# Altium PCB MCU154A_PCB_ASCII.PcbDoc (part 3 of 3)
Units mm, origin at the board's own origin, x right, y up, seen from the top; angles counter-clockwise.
Board outline 105 x 85 mm, 2 copper layers (Top Layer, Bottom Layer), stack 1.6 mm thick; 186 components, 100 nets, 433 pads, 196 vias.
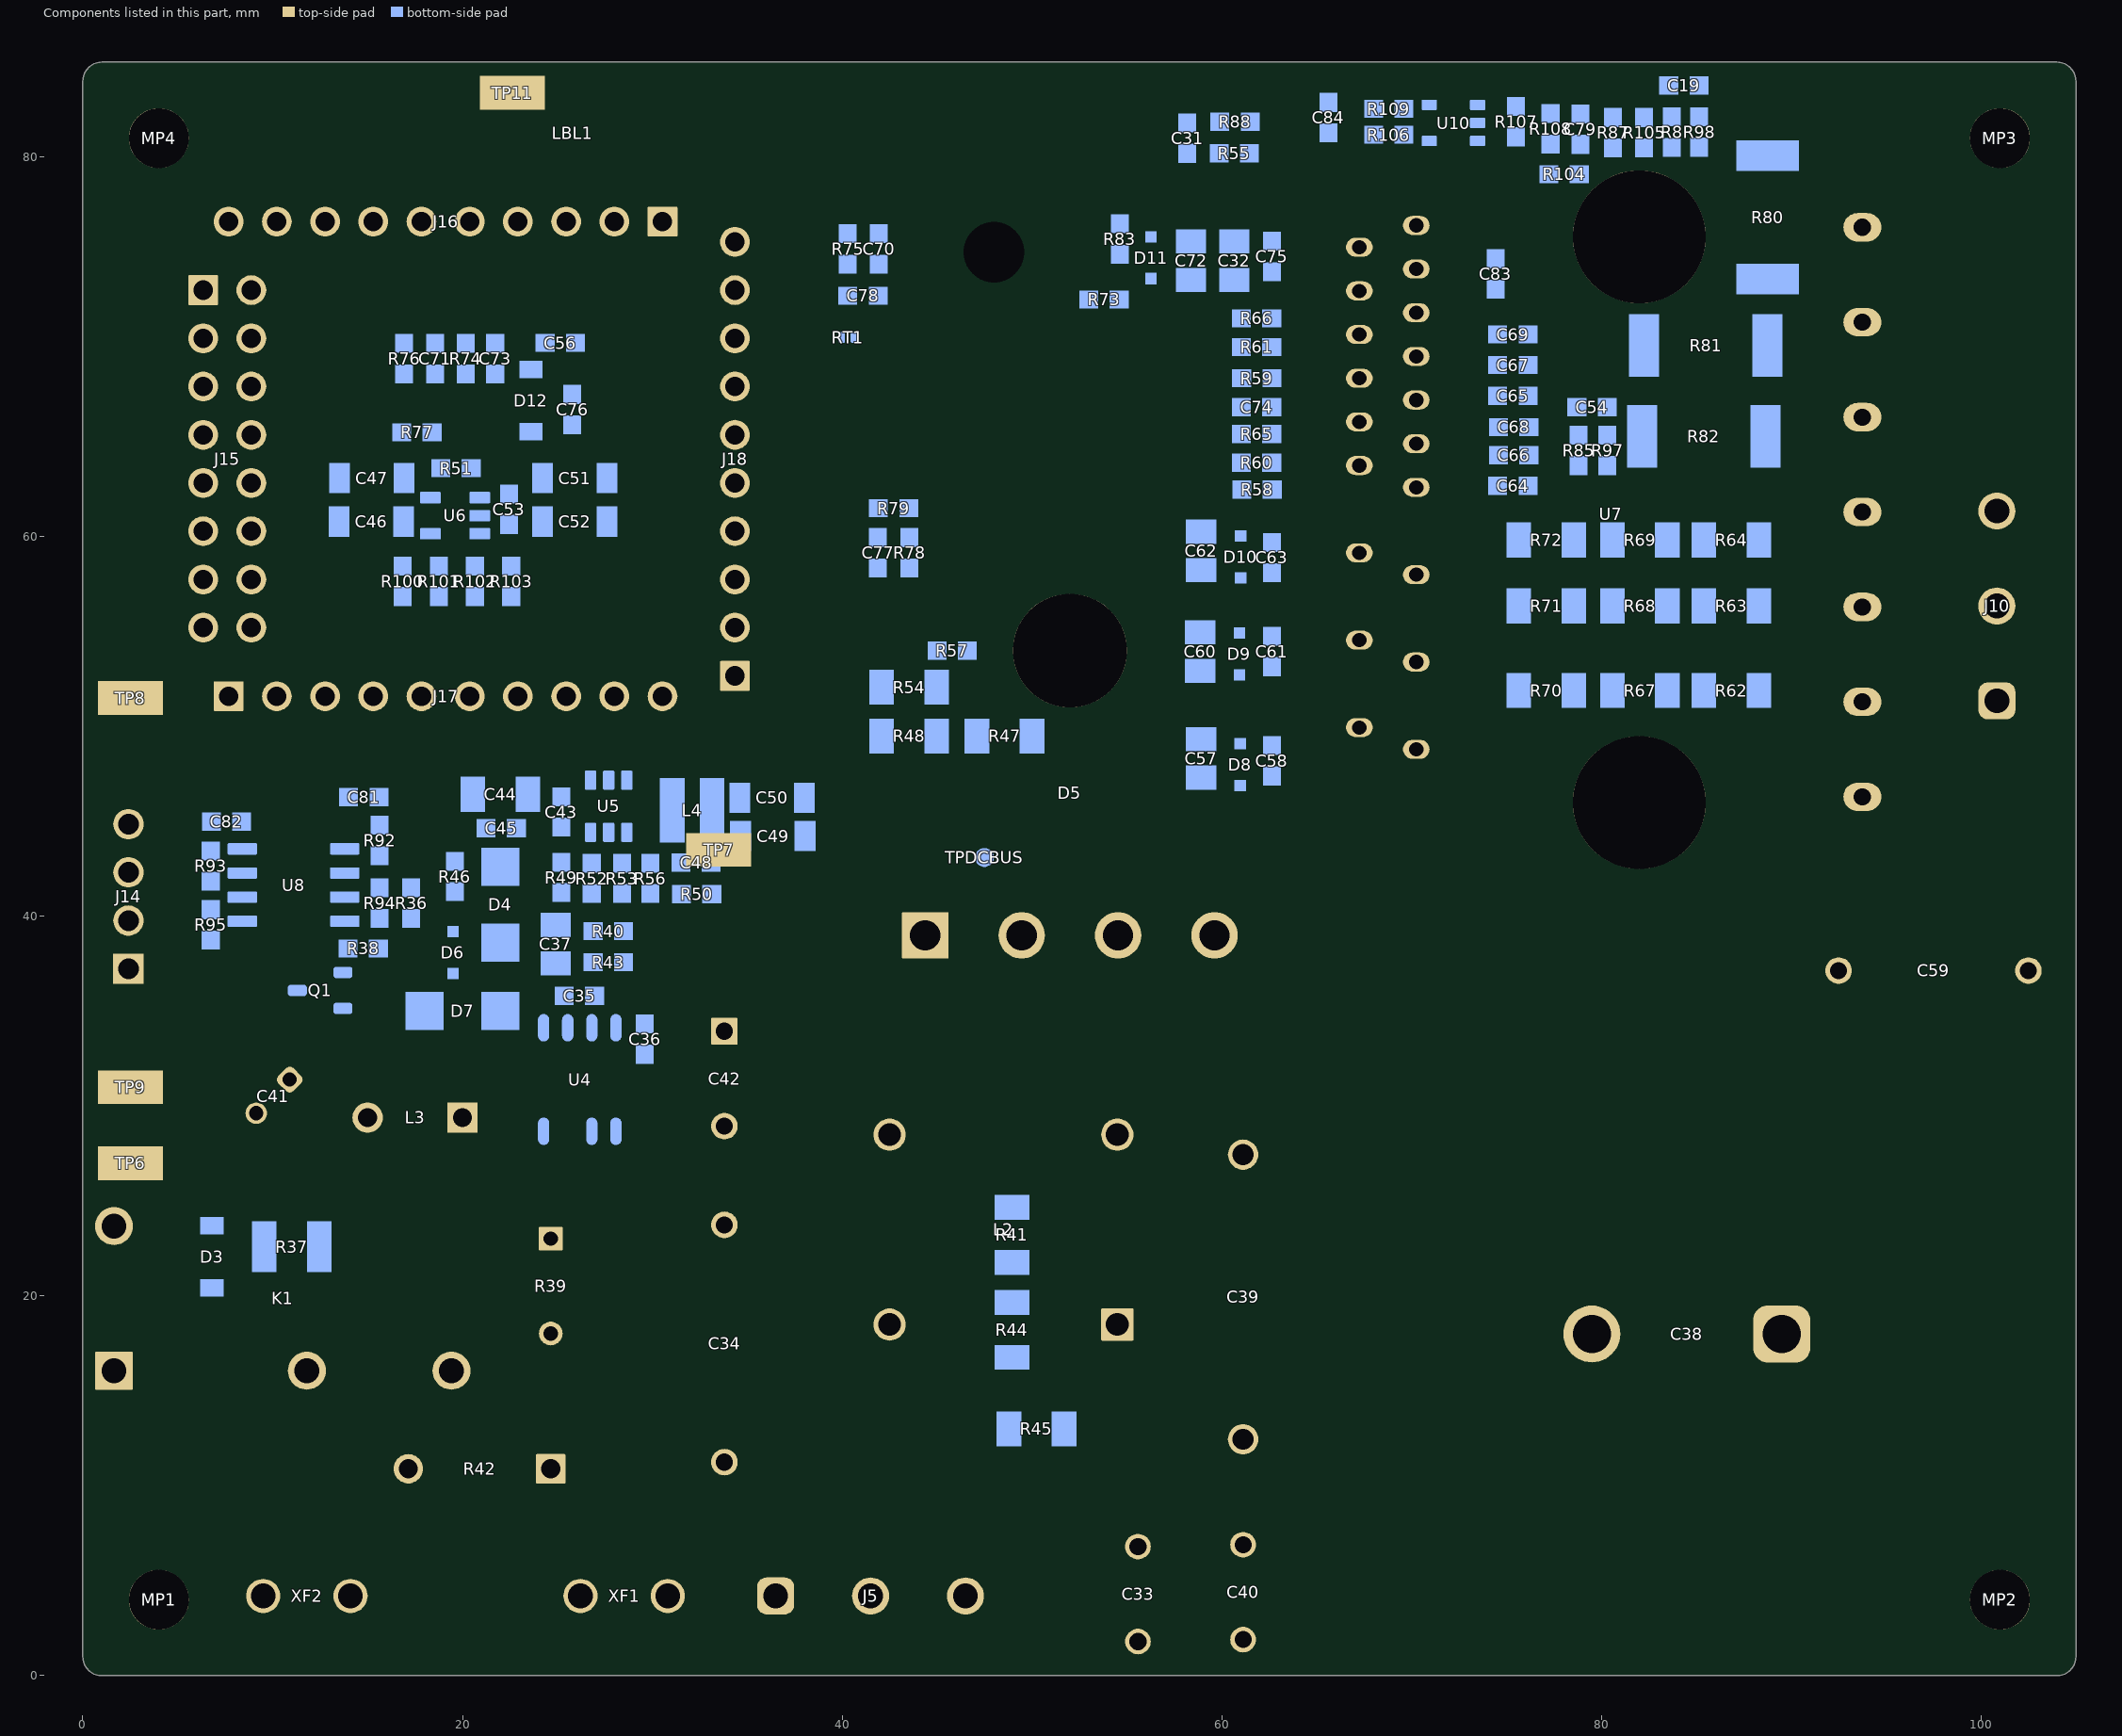
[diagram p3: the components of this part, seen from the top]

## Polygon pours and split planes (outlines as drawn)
NetC35_2 on Bottom Layer "TOP_LAYER_NONET_P-001" (solid, pour order 93): 20.909,33.309 18.616,31.016 18.616,28.772 18.907,28.481 20.862,28.481 21.238,28.857 21.238,30.171 24.11,33.044 25.531,33.044 25.545,33.029 25.931,33.415 25.931,36.75 25.923,36.851 26.13,37.058 27.259,37.058 27.4,37.199 27.4,38.1 27.3,38.2 24.332,38.2 22.332,36.2 21.17,36.2 20.909,35.94
MOTOR_V on Bottom Layer "TOP_LAYER_NONET_P-001" (solid, pour order 89): 92.18,54.223 91.853,54.55 91.853,57.925 92.328,58.4 102.868,58.4 103.389,57.6 103.389,54.9 102.868,54.223
MOTOR_W on Bottom Layer "TOP_LAYER_NONET_P-001" (solid, pour order 88): 93.13,59.616 92.405,60.34 92.405,62.047 93.144,62.786 96.301,62.786 97.675,64.161 98.283,64.5 104.102,64.5 104.5,64.161 104.5,62.21 101.913,59.623
MOTOR_U on Bottom Layer "TOP_LAYER_NONET_P-001" (solid, pour order 87): 92.405,52.8 91.9,52.295 91.9,49.826 92.556,49.17 95.677,49.17 99.193,47.7 103.055,47.7 104.5,49.17 104.5,50.3 102,52.8
EGND on Bottom Layer "TOP_LAYER_NONET_P-001" (solid, pour order 86): 45.4,4.2 45.4,1.3 46.2,0.6 62.388,0.6 63.188,1.4 63.188,2.512 62.7,3 49.47,3 48.789,3.681 48.789,6.9 48.359,6.9 45.8,6.9 45.4,6.389
NEU on Bottom Layer "TOP_LAYER_NONET_P-001" (solid, pour order 20): 22.3,10.3 23.1,9.5 37.8,9.5 40,7.3 40,3.3 40.7,2.512 42.5,2.512 43,3.2 43,7.7 44.8,9.5 44.8,19.48 44.28,20 38.898,20 34.058,15.16 31.498,12.6 23.12,12.6 22.3,11.78
LINE on Bottom Layer "TOP_LAYER_NONET_P-001" (solid, pour order 51): 22,1.3 22.6,0.7 36.3,0.7 37.7,2.1 37.7,5.7 36.5,6.9 22.5,6.9 22,6.4
5V on Bottom Layer "T-G" (solid, remove dead copper, pour order 83): 23.116,61.7 23.92,60.895 24.756,60.895 24.756,64.068 24.591,64.233 20.218,64.233 19.968,63.983 19.968,62.422 19.247,61.7 19.247,59.705 19.403,59.549 21.643,59.549 21.674,59.579 21.674,60.323 21.533,60.463 20.068,60.463 19.968,60.563 19.968,61.363 20.305,61.7
5V on Bottom Layer "B-5V" (solid, remove dead copper, pour order 84): 32.5,47.309 34.844,47.309 35.399,46.754 35.399,40.395 35.108,40.103 33.037,40.103 32.5,40.64
Ubus on Bottom Layer "Bottom Layer-Ubus" (solid, pour order 16): 91.438,0.6 103.77,12.932 103.77,38.93 95,47.7 92.69,47.7 92.319,47.328 92.319,41.378 95.5,38.196 95.5,35.935 94.531,34.966 92.306,34.966 85.972,41.3 80.866,41.3 76.571,45.595 55.965,45.595 54.379,47.181 41.932,47.181 40.764,46.013 40.764,37.615 41.302,36.75 45.768,36.75 46.268,37.25 46.268,41.214 47.105,42.052 62.554,42.052 70.25,34.355 70.25,2.343 71.993,0.6
NetR8_1 on Bottom Layer "Bottom Layer-NetR8_1" (solid, pour order 80): 94.716,73.06 103.571,73.06 104.23,73.718 104.23,76.505 103.777,76.957 98.863,76.957 96.7,79.12 96.7,83.613 96.223,84.09 91.761,84.09 91.216,83.545 91.216,78.53 91.204,78.518 91.204,77.912 88.856,75.564 87.358,75.564 85.803,75.564 85.397,75.158 85.397,73.157 85.837,72.717 90.254,72.717 90.59,73.053 94.709,73.053
GND on Bottom Layer "Bottom Layer-GND" (solid, pour order 74): 85.874,78.556 86.88,77.55 89.757,77.55 90.59,78.384 90.59,84.26 90.276,84.574 86.616,84.574 85.874,83.833
NetR55_1 on Bottom Layer "Bottom Layer-NetR55_1" (solid, pour order 78): 88.002,68.059 89.581,68.059 89.581,68.068 90.478,68.068 91.035,68.624 95.103,68.624 96.473,69.994 104.004,69.994 104.004,72.307 103.594,72.717 93.7,72.717 93.7,72.723 93.694,72.717 91.684,72.717 90.724,71.757 86.357,71.757 85.96,71.36 85.96,68.523 86.423,68.059 88.002,68.059
NetC34_1 on Bottom Layer "TOP_LAYER_NONET_P-001" (solid, pour order 53): 17,18.6 19.5,21.1 26.711,21.1 31.512,25.901 36.299,25.901 41.283,30.886 44.196,30.886 45.19,29.892 45.19,23.223 43.9,21.933 38.033,21.933 30.75,14.65 17.25,14.65 17,14.9
NetK1_2 on Bottom Layer "TOP_LAYER_NONET_P-001" (solid, pour order 50): 8,0.988 8,8 6.093,9.907 6.093,17.402 7.291,18.6 13.3,18.6 15.055,16.845 15.055,15.525 18.5,12.08 18.5,1.6 17.5,0.6 8.3,0.6
NetR82_2 on Bottom Layer "TOP_LAYER_NONET_P-001" (solid, pour order 33): 90.265,66.924 91.622,68.281 94.813,68.281 95.2,67.893 95.2,64.815 94.709,64.325 91.761,64.325 91.091,63.654 87.916,63.654 87.916,66.826 88.015,66.924
NetR82_2 on Bottom Layer "TOP_LAYER_NONET_P-001" (solid, pour order 32): 89.495,63.373 86.338,63.373 85.874,63.836 85.874,66.673 86.271,67.07 89.388,67.07 89.495,66.963
GND on Bottom Layer "TOP_LAYER_NONET_P-001" (solid, pour order 29): 81.376,71.925 84.633,71.925 85.097,71.462 85.097,68.624 84.7,68.228 81.583,68.228 81.376,68.434
GND on Bottom Layer "TOP_LAYER_NONET_P-001" (solid, pour order 28): 81.376,67.297 84.533,67.297 84.997,66.834 84.997,63.997 84.6,63.6 81.483,63.6 81.376,63.707
Ubus on Bottom Layer "TOP_LAYER_NONET_P-001" (solid, pour order 17): 23.583,29.25 23.583,27.225 24.058,26.75 34.221,26.75 35.724,28.253 35.724,29.255 34.811,30.168 31.514,30.168 30.815,29.469 28.013,29.469 27.68,29.136 27.68,27.861 27.587,27.768 24.83,27.768 24.65,27.948 24.65,29.291 24.472,29.469 23.809,29.469
NetC39_2 on Bottom Layer "TOP_LAYER_NONET_P-001" (solid, pour order 6): 53.511,21.488 63.188,21.488 64.644,22.944 64.644,29.931 63.247,31.328 56.61,31.328 53.1,34.838 53.1,39.9 53.762,40.562 55.624,40.562 55.9,40.285 55.9,36.65 57.55,35 65.2,35 68.4,31.8 68.4,19.1 65.2,15.9 65.1,16 53.19,16 52.387,16.803 52.387,20.469
NetC33_1 on Bottom Layer "TOP_LAYER_NONET_P-001" (solid, pour order 5): 48.712,24 47.99,24.722 47.99,39.645 48.907,40.562 50.239,40.562 50.9,39.901 50.9,33.981 55.826,29.054 61.283,29.054 62.198,28.14 62.198,24.694 61.504,24
GND_ISO on Top Layer "T-G" (solid, remove dead copper, pour order 94): 8.9,46.25 0.9,46.25 0.7,46.05 0.7,36.174 1.024,35.85 5.45,35.85 9.2,39.6 9.2,45.95
GND on Top Layer "Top Layer-GND 1" (solid, remove dead copper, pour order 64): 19.5,36.502 20.068,37.071 20.068,40.068 20.424,40.424 29.702,40.424 29.998,40.078 31.544,38.531 31.544,33.388 32.196,32.737 35.107,32.737 35.661,33.29 35.661,37.268 38.729,40.336 38.729,47.732 39.797,48.8 47.74,48.8 48.7,49.76 48.7,55.495 55.242,62.037 73.539,62.037 74.153,61.423 74.153,50.69 74.594,50.249 76.279,50.249 77.365,51.334 77.365,60.129 79.027,61.791 80.146,61.791 80.579,62.224 80.579,72.27 78.541,74.307 78.541,77.41 80.552,79.421 85.293,79.421 85.627,79.756 85.627,84.384 85.211,84.8 9.7,84.8 8.484,83.584 8.484,78.408 7.676,77.6 2.034,77.6 0.706,76.272 0.706,50 10.116,50 13,47.085 13,38.627 6.373,32 0.6,32 0.6,26.227 1.069,25.758 15.988,25.758 16.5,26.27 16.5,31.166 18.722,33.388 19.5,34.166
MOTOR_V on Top Layer "TOP_LAYER_NONET_P-001" (solid, pour order 26): 92.18,54.223 91.853,54.55 91.853,57.925 92.328,58.4 102.868,58.4 103.389,57.6 103.389,54.9 102.868,54.223
MOTOR_U on Top Layer "TOP_LAYER_NONET_P-001" (solid, pour order 24): 92.405,52.8 91.9,52.295 91.9,49.826 92.556,49.17 95.677,49.17 99.193,47.7 103.055,47.7 104.5,49.17 104.5,50.3 102,52.8
MOTOR_W on Top Layer "TOP_LAYER_NONET_P-001" (solid, pour order 25): 93.13,59.616 92.405,60.34 92.405,62.047 93.144,62.786 96.301,62.786 97.675,64.161 98.283,64.5 104.102,64.5 104.5,64.161 104.5,62.21 101.913,59.623
EGND on Top Layer "TOP_LAYER_NONET_P-001" (solid, pour order 54): 45.4,4.2 45.4,1.3 46.2,0.6 62.388,0.6 63.188,1.4 63.188,2.512 62.7,3 49.47,3 48.789,3.681 48.789,6.9 48.359,6.9 45.8,6.9 45.4,6.389
NEU on Top Layer "TOP_LAYER_NONET_P-001" (solid, pour order 85): 22.3,10.3 23.1,9.5 37.8,9.5 40,7.3 40,3.3 40.7,2.512 42.5,2.512 43,3.2 43,7.7 44.8,9.5 44.8,19.48 44.28,20 38.898,20 34.058,15.16 31.498,12.6 23.12,12.6 22.3,11.78
LINE on Top Layer "TOP_LAYER_NONET_P-001" (solid, pour order 19): 22,1.3 22.6,0.7 36.3,0.7 37.7,2.1 37.7,5.7 36.5,6.9 22.5,6.9 22,6.4
GND on Top Layer "Top Layer-GND" (solid, pour order 82): 57.876,38.224 58.731,37.369 64.852,37.369 70.25,31.971 70.25,2.45 72.1,0.6 91.438,0.6 103.9,13.062 103.9,29.745 94.164,39.481 92.325,41.32 92.312,41.32 89.283,44.349 89.283,76.766 89.474,76.957 90.59,78.074 90.59,84.26 90.276,84.574 86.616,84.574 85.902,83.861 85.902,79.22 85.346,78.664 85.346,74.379 83.275,72.307 81.607,72.307 81.1,71.8 81.1,50.249 81.42,49.929 83.703,49.929 85.589,48.043 85.589,43.147 84.437,41.994 80.146,41.994 77.111,45.029 59.256,45.029 57.876,43.648
NetC33_1 on Top Layer "TOP_LAYER_NONET_P-001" (solid, pour order 55): 49.913,24 47.99,25.923 47.99,39.645 48.907,40.562 50.239,40.562 50.9,39.901 50.9,33.981 55.826,29.054 61.283,29.054 62.198,28.14 62.198,24.694 61.504,24
NetR55_1 on Top Layer "Top Layer-NetR55_1" (solid, pour order 77): 89.513,68.068 90.478,68.068 91.035,68.624 95.103,68.624 96.473,69.994 104.004,69.994 104.004,72.307 103.594,72.717 93.7,72.717 93.7,72.723 93.694,72.717 91.684,72.717 90.724,71.757 89.513,71.757
NetR8_1 on Top Layer "Top Layer-NetR8_1" (solid, pour order 70): 94.716,73.06 103.571,73.06 104.23,73.718 104.23,76.505 103.777,76.957 98.863,76.957 96.7,79.12 96.7,83.613 96.223,84.09 91.761,84.09 91.216,83.545 91.216,78.53 91.204,78.518 91.204,77.912 90.141,76.849 89.498,76.206 89.498,72.717 90.254,72.717 90.59,73.053 94.709,73.053
NetR82_2 on Top Layer "TOP_LAYER_NONET_P-001" (solid, pour order 39): 89.547,66.938 90.281,66.94 91.622,68.281 94.813,68.281 95.2,67.893 95.2,64.815 94.709,64.325 91.761,64.325 91.072,63.636 89.547,63.636
Ubus on Top Layer "TOP_LAYER_NONET_P-001" (solid, pour order 60): 94.999,47.7 103.9,38.799 103.9,35.896 103.658,35.654 102.275,35.654 101.002,36.927 93.791,44.138 92.319,45.61 92.319,47.328 92.69,47.7
NetC39_2 on Top Layer "TOP_LAYER_NONET_P-001" (solid, pour order 56): 53.511,21.488 63.188,21.488 64.644,22.944 64.644,29.931 63.247,31.328 56.61,31.328 53.1,34.838 53.1,39.9 53.762,40.562 55.624,40.562 55.9,40.285 55.9,36.65 57.55,35 65.2,35 68.4,31.8 68.4,19.1 65.2,15.9 65.1,16 53.19,16 52.387,16.803 52.387,20.469
NetC34_1 on Top Layer "TOP_LAYER_NONET_P-001" (solid, pour order 21): 17.611,19.211 19.1,20.7 26.311,20.7 31.512,25.901 36.299,25.901 41.283,30.886 44.196,30.886 45.19,29.892 45.19,23.223 43.9,21.933 38.033,21.933 30.75,14.65 18.121,14.65 17.611,15.16
NetK1_2 on Top Layer "TOP_LAYER_NONET_P-001" (solid, pour order 18): 8,0.988 8,8 6.093,9.907 6.093,17.402 7.291,18.6 13.283,18.6 15.055,16.829 15.055,15.345 18.5,11.9 18.5,1.6 17.5,0.6 8.3,0.6

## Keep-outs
Top Layer:
  circle w0.254: c48,75 r2.5
Bottom Layer:
  circle w0.254: c48,75 r3.5
Keep-Out Layer:
  circle w0.254: c4,81 r4
  circle w0.254: c101,81 r4
  circle w0.254: c101,4 r4
  circle w0.254: c4,4 r4
  text ".Layer_Name" at 14.656,-21.806 h1.52

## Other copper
Top Layer:
  text ".Layer_Name" at 14.656,-21.806 h1.52
Bottom Layer:
  text ".Layer_Name" at 14.656,-21.806 h1.52

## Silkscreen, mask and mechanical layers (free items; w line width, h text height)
Top Overlay:
  circle w0.254: c84.5,18 r15.892
  lines w0.2: 0.86,56.44 4.86,56.44 ; 0.86,59.94 4.86,59.94 ; 0.86,61.94 4.86,61.94 ; 0.86,64.94 4.86,64.94 ; 0.86,67.94 4.86,67.94 ; 0.86,70.94 4.86,70.94 ; 0.86,73.94 4.86,73.94 ; 2.86,52.94 2.86,76.94 ; 6.464,39.394 9.6,39.394 ; 6.464,41.015 9.6,41.015 ; 6.464,42.614 9.6,42.614 ; 6.469,44.063 9.6,44.063 9.6,37.906 9.568,37.874 6.481,37.874 ; 8.95,78.194 8.95,82.194 ; 9.55,45.206 9.55,49.706 ; 11.49,82.194 11.49,78.194 ; 12.09,45.206 12.09,49.706 ; 14.03,78.194 14.03,82.194 ; 14.63,45.206 14.63,49.706 ; 16.57,78.194 16.57,82.194 ; 17.17,45.206 17.17,49.706 ; 19.11,78.194 19.11,82.194 ; 19.71,45.206 19.71,49.706 ; 21.65,82.194 21.65,78.194 ; 22.25,45.206 22.25,49.706 ; 24.19,82.194 24.19,78.194 ; 24.79,45.206 24.79,49.706 ; 26.73,82.194 26.73,78.194 ; 27.33,45.206 27.33,49.706 ; 29.27,78.194 29.27,82.194 ; 29.87,45.206 29.87,49.706 ; 36.354,53.94 39.354,53.94 ; 36.354,64.1 39.354,64.1 ; 36.354,66.64 39.354,66.64 ; 36.354,69.18 39.354,69.18 ; 36.354,74.26 39.354,74.26 ; 39.354,56.48 36.354,56.48 ; 39.354,59.02 36.354,59.02 ; 39.354,61.56 36.354,61.56 ; 39.354,71.72 36.354,71.72 ; 11.49,78.194 21.65,78.194 ; 11.49,78.194 6.41,78.194 6.41,82.194 31.81,82.194 31.81,78.194 26.73,78.194 ; 21.65,78.194 24.19,78.194 ; 24.19,78.194 26.73,78.194 ; 36.354,56.48 36.354,51.4 39.354,51.4 39.354,76.8 36.354,76.8 36.354,71.72 ; 36.354,56.48 36.354,59.02 ; 36.354,59.02 36.354,61.56 ; 36.354,61.56 36.354,71.72 ; 0.86,52.94 0.86,76.94 4.86,76.94 4.86,52.94 0.86,52.94 ; 7.01,45.206 7.01,49.706 32.41,49.706 32.41,45.206 7.01,45.206
  text "GND" at 25.3,82.9 h0.9
  text "IUN" at 8.17,79.025 h0.9 r90
  text "IUP" at 10.721,79.025 h0.9 r90
  text "IVN" at 13.272,79.025 h0.9 r90
  text "IVP" at 15.823,79.025 h0.9 r90
  text "IWN" at 25.928,79.025 h0.9 r90
  text "IWP" at 28.479,79.025 h0.9 r90
  text "GND" at 18.375,78.95 h0.9 r90
  text "VWAD" at 20.826,78.683 h0.8 r90
  text "VUAD" at 23.377,78.5 h0.9 r90
  text "VVAD" at 31.03,78.5 h0.9 r90
  text "VDC" at 36.608,75.04 h0.9
  text "3V3" at 2.3,74.26 h0.9 r90
  text "GND" at 4.3,74.26 h0.9 r90
  text "IPM" at 36.683,72.5 h0.9
  text "TMS" at 2.3,71.14 h0.9 r90
  text "TCK" at 4.3,71.14 h0.9 r90
  text "MOT" at 36.608,69.96 h0.9
  text "W" at 101.15,69.758 h1.5 r90
  text "TDI" at 2.3,68.4 h0.9 r90
  text "TDO" at 4.3,68.14 h0.9 r90
  text "WH" at 37.058,67.42 h0.9
  text "V" at 101.206,67.32 h1.5 r90
  text "GND" at 2.3,65.2 h0.9 r90
  text "WL" at 37.058,64.88 h0.9
  text "RX" at 2.3,62.7 h0.9 r90
  text "TX" at 4.3,62.7 h0.9 r90
  text "GND" at 36.608,62.204 h0.9
  text "UH" at 37.058,59.8 h0.9
  text "UL" at 37.058,57.26 h0.9
  text "CLK" at 2.3,57.1 h0.9 r90
  text "PICO" at 4.3,56.64 h0.9 r90
  text "VH" at 37.058,54.72 h0.9
  text "POCI" at 2.3,53.2 h0.9 r90
  text "PTE" at 4.3,53.2 h0.9 r90
  text "VL" at 37.058,52.18 h0.9
  text "3.3V" at 3.215,49.1 h0.8
  text "IO" at 11.31,46.885 h0.9 r90
  text "CLK" at 18.93,46.36 h0.9 r90
  text "PTE" at 21.47,46.36 h0.9 r90
  text "3V3" at 26.55,46.36 h0.9 r90
  text "GND" at 29.09,46.36 h0.9 r90
  text "POCI" at 24.01,46.06 h0.9 r90
  text "PICO" at 16.39,45.985 h0.9 r90
  text "RELAY" at 8.77,45.46 h0.9 r90
  text "FAULT" at 31.63,45.46 h0.9 r90
  text "U" at 101.498,44.5 h1.5 r90
  text "Isolated UART" at 10.049,43.892 h0.75 r270
  text "5V" at 31.967,41.1 h0.8
  text "5V / RX / TX / GND" at 6.737,38.026 h0.9
  text "'.PRJ_TITLE' / '.PRJ_Number'.PCB_Rev" at 64.376,34.594 h2.75
  text "GND" at 3.687,32.601 h0.8
  text "15V" at 3.437,28.611 h0.8
  text "+" at 94.265,17.295 h1.25
  text "拼板" at 397.247,13.207 h4
  text "L" at 36.05,8.15 h1.5
  text "N" at 40.95,8.05 h1.5
  text "E" at 46.05,7.95 h1.5
  text ".Layer_Name" at 14.656,-21.806 h1.52
Bottom Overlay:
  lines w0.2: 29.892,40.476 30.267,40.101 31.6,40.101 32,39.701 ; 86.24,81.914 86.655,81.914 ; 86.254,82.489 86.254,81.928 86.226,81.9 87.033,82.707 88.347,82.707
  lines w0.254: 62.78,4.194 79.98,4.194 ; 62.78,7.194 79.98,7.194 ; 65.422,10.094 65.481,1.358 ; 94.05,20.722 102.75,20.781 ; 97.05,7.081 97.05,35.261 ; 99.95,7.081 99.95,35.201 ; 62.78,1.358 79.98,1.358 79.98,10.094 62.78,10.094 62.78,1.358 ; 94.05,7.081 94.05,35.261 102.85,35.261 102.85,7.081 94.05,7.081
  text "W" at 99.358,61.904 h1.5 r90
  text "V" at 99.369,56.847 h1.5 r90
  text "U" at 99.381,51.757 h1.5 r90
  text "'.Output_P' / '.Output_I' / '.Output_F_Motor'" at 102.75,35.081 h2 r90
  text "Rated Output Spec to Motor" at 93.55,35.061 h0.9 r90
  text "P / I / Motor F" at 102.75,20.725 h2 r90
  text "Rated AC Input Spec" at 79.78,10.594 h0.9
  text "L" at 37.15,5.638 h1.5
  text "N" at 42.05,5.538 h1.5
  text "E" at 47.15,5.438 h1.5
  text "V / I / F" at 65.2,1.494 h2
  text "'.Input_V' / '.Input_I' / '.Input_F'" at 79.8,1.494 h2
  text ".Layer_Name" at 14.656,-21.806 h1.52
Top Paste:
  text ".Layer_Name" at 14.656,-21.806 h1.52
Bottom Paste:
  text ".Layer_Name" at 14.656,-21.806 h1.52
Top Solder:
  text ".Layer_Name" at 14.656,-21.806 h1.52
  text ".Layer_Name" at 14.656,-21.806 h1.52
Bottom Solder:
  text ".Layer_Name" at 14.656,-21.806 h1.52
Drill Guide:
  text ".Layer_Name" at 14.656,-21.806 h1.52
M1 Board Outline:
  lines w0.2: 38.348,6.7 cw(c38.848,6.7) 39.348,6.7 39.348,1.5 cw(c38.848,1.5) 38.348,1.5 38.348,6.7 ; 44.651,1.5 44.651,6.7 ccw(c44.151,6.7) 43.651,6.7 43.652,1.5 ccw(c44.151,1.5) 44.651,1.5 ; 395.6,32.8 cw(c395.6,33.8) 394.6,33.8 394.6,136.8 cw(c395.6,136.8) 395.6,137.8 ; 395.6,32.8 cw(c395.6,32.3) 395.6,31.8 394.6,31.8 394.6,29.8 ccw(c396.6,29.8) 396.6,27.8 562.6,27.8 ccw(c562.6,29.8) 564.6,29.8 564.6,31.8 563.6,31.8 cw(c563.6,32.3) 563.6,32.8 ; 395.6,32.8 478.6,32.8 ; 395.6,137.8 ccw(c395.6,138.3) 395.6,138.8 394.6,138.8 394.6,140.8 cw(c396.6,140.8) 396.6,142.8 562.6,142.8 cw(c562.6,140.8) 564.6,140.8 564.6,138.8 563.6,138.8 ccw(c563.6,138.3) 563.6,137.8 ; 395.6,137.8 478.6,137.8 ; 478.6,32.8 ccw(c478.6,33.8) 479.6,33.8 ; 478.6,32.8 ccw(c478.6,32.3) 478.6,31.8 480.6,31.8 ccw(c480.6,32.3) 480.6,32.8 ; 478.6,137.8 cw(c478.6,136.8) 479.6,136.8 ; 478.6,137.8 cw(c478.6,138.3) 478.6,138.8 480.6,138.8 cw(c480.6,138.3) 480.6,137.8 ; 479.6,33.8 ccw(c480.6,33.8) 480.6,32.8 ; 479.6,33.8 479.6,136.8 ; 479.6,33.8 479.6,136.8 ; 479.6,136.8 cw(c480.6,136.8) 480.6,137.8 ; 480.6,32.8 563.6,32.8 ; 480.6,137.8 563.6,137.8 ; 563.6,32.8 ccw(c563.6,33.8) 564.6,33.8 564.6,136.8 ccw(c563.6,136.8) 563.6,137.8 ; 0,1 ccw(c1,1) 1,0 104,0 ccw(c104,1) 105,1 105,84 ccw(c104,84) 104,85 1,85 ccw(c1,84) 0,84 0,1 ; 4.36,50.6 ccw(c5.36,50.6) 5.36,49.6 35.36,49.6 ccw(c35.36,50.6) 36.36,50.6 36.36,77.6 ccw(c35.36,77.6) 35.36,78.6 5.36,78.6 ccw(c5.36,77.6) 4.36,77.6 4.36,50.6 ; 92.017,47.918 cw(c92.017,48.418) 92.017,48.918 95.6,48.918 99.673,44.845 cw(c99.319,44.491) 98.966,44.138 95.185,47.918 92.017,47.918 ; 92.017,52.995 cw(c92.017,53.495) 92.017,53.995 103,53.995 cw(c103,53.495) 103,52.995 92.017,52.995 ; 92.209,58.554 cw(c92.209,59.054) 92.209,59.554 103,59.554 cw(c103,59.054) 103,58.554 92.209,58.554 ; 92.695,63.017 cw(c92.695,63.517) 92.695,64.017 95.402,64.017 95.514,64.017 95.988,64.492 95.988,66.431 cw(c96.488,66.431) 96.988,66.431 96.988,64.115 95.89,63.017 92.695,63.017
  text ".Layer_Name" at 14.656,-21.806 h1.52
M2 Board Dimensions:
  rectangle: 0,-6.985 3.175,-3.81
  rectangle: 3.175,-10.16 12.7,-6.985
  lines w0.178: 0,-6.985 25.4,-6.985 ; 3.175,-10.16 3.175,-3.81 ; 6.35,-10.16 6.35,-3.81 ; 12.7,-10.16 12.7,-3.81 ; 19.05,-10.16 19.05,-3.81 ; 0,-10.16 25.4,-10.16 25.4,-3.81 0,-3.81 0,-10.16
  lines w0.254: 40.5,41 95.5,41 95.5,81 40.5,81 40.5,41
  text "41.5,34.8" at 87.948,77.32 h0.8
  text "7.5,34" at 43.5,69.067 h0.8
  text "11.5,13" at 46.9,48.618 h0.8
  text "41.5,5" at 79.691,38.704 h0.8
  text ".Layer_Name" at 14.656,-21.806 h1.52
M3 3D STEP Top:
  text ".Layer_Name" at 14.656,-21.806 h1.52
M4 3D STEP Bottom:
  text ".Layer_Name" at 14.656,-21.806 h1.52
M5 Assembly Top:
  lines w0.254: -7.417,-23.626 160.223,-23.626 ; -7.417,-18.462 160.274,-18.462 ; -7.417,-13.297 -7.417,-28.791 94.31,-28.791 160.274,-28.791 160.274,-13.297 -7.404,-13.297 -7.404,-28.791 32.614,-28.791 ; 55.194,-28.791 55.194,-13.297 ; 87.376,-18.462 87.376,-13.297 ; 108.712,-18.462 108.712,-13.297 ; 124.511,-28.956 124.511,-23.804
  text "COMPONENTS MARKED 'DNP' SHOULD NOT BE POPULATED." at 29.299,-8.09 h0.8
  text "ASSEMBLY VARIANT:" at 29.286,-11.024 h0.8
  text ".VariantName" at 55.601,-11.024 h0.8
  text "PCB VIEWED FROM TOP SIDE" at -5.804,-16.654 h1.52
  text "BOARD #:" at 57.099,-16.654 h1.52
  text ".PRJ_Number" at 70.955,-16.654 h1.52
  text "REV:" at 92.405,-16.654 h1.52
  text ".PCB_Rev" at 99.809,-16.654 h1.52
  text "SVN REV:" at 113.69,-16.654 h1.52
  text ".VersionControl_RevNumber" at 126.543,-16.654 h1.52
  text "TID #:" at 57.099,-21.819 h1.52
  text ".TID" at 70.955,-21.819 h1.52
  text "PLOT NAME =" at -5.804,-27.034 h1.52
  text ".plot_File_Name" at 14.656,-27.034 h1.52
  text "GENERATED    :" at 57.15,-27.034 h1.52
  text ".Print_Date" at 79.235,-27.034 h1.52
  text ".Print_Time" at 97.752,-27.034 h1.52
  text "TEXAS INSTRUMENTS" at 129.87,-27.034 h1.52
M6 Assembly Bottom:
  lines w0.254: -7.429,-18.474 160.261,-18.474 ; -7.379,-23.639 160.261,-23.639 ; 28.334,-28.969 28.334,-23.817 ; 44.133,-18.474 44.133,-13.31 ; 65.468,-18.474 65.468,-13.31 ; 97.65,-28.804 97.65,-13.31 ; 120.231,-28.804 160.249,-28.804 160.249,-13.31 -7.429,-13.31 -7.429,-28.804 58.534,-28.804 160.261,-28.804 160.261,-13.31
  text "COMPONENTS MARKED 'DNP' SHOULD NOT BE POPULATED." at 154.991,-8.077 h0.8
  text ".VariantName" at 128.473,-11.024 h0.8
  text "ASSEMBLY VARIANT:" at 154.864,-11.024 h0.8
  text ".VersionControl_RevNumber" at 26.302,-16.667 h1.52
  text "SVN REV:" at 39.154,-16.667 h1.52
  text ".PCB_Rev" at 53.035,-16.667 h1.52
  text "REV:" at 60.439,-16.667 h1.52
  text ".PRJ_Number" at 81.89,-16.667 h1.52
  text "BOARD #:" at 95.745,-16.667 h1.52
  text "PCB VIEWED FROM BOTTOM SIDE" at 158.648,-16.667 h1.52
  text ".TID" at 81.89,-21.831 h1.52
  text "TID #:" at 95.745,-21.831 h1.52
  text "TEXAS INSTRUMENTS" at 22.974,-27.047 h1.52
  text ".Print_Time" at 55.093,-27.047 h1.52
  text ".Print_Date" at 73.609,-27.047 h1.52
  text "GENERATED    :" at 95.694,-27.047 h1.52
  text ".plot_File_Name" at 138.189,-27.047 h1.52
  text "PLOT NAME =" at 158.648,-27.047 h1.52
M9 Title Sheet:
  lines w0.254: -12.484,26.454 -7.404,26.454 ; -12.484,86.779 -7.404,86.779 ; -12.484,147.104 -7.404,147.104 ; 51.016,-33.871 51.016,-28.791 ; 51.016,202.349 51.016,207.429 ; 114.516,-33.871 114.516,-28.791 ; 114.516,202.349 114.516,207.429 ; 160.553,-28.791 160.553,-13.297 287.109,-13.297 ; 178.016,-33.871 178.016,-28.791 ; 178.016,202.349 178.016,207.429 ; 241.516,-33.871 241.516,-28.791 ; 241.516,202.349 241.516,207.429 ; 287.109,-28.791 287.109,-13.297 ; 287.109,-20.917 363.309,-20.917 ; 287.109,-5.677 363.309,-5.677 ; 287.134,9.411 363.334,9.411 ; 305.016,-33.871 305.016,-28.791 ; 305.016,202.349 305.016,207.429 ; 325.336,-28.537 325.336,-13.297 ; 363.309,-13.297 287.109,-13.297 ; 363.309,1.943 287.109,1.943 ; 363.436,1.689 363.436,-28.791 ; 363.436,22.123 287.134,22.123 287.109,22.123 287.109,9.411 287.109,1.943 ; 363.436,26.454 368.516,26.454 ; 363.436,86.779 368.516,86.779 ; 363.436,147.104 368.516,147.104 ; 287.109,-13.297 287.109,1.943 ; 363.436,-28.791 363.436,202.349 -7.404,202.349 -7.404,-28.791 363.436,-28.791 ; -12.484,-33.871 -12.484,207.429 368.516,207.429 368.516,-33.871 -12.484,-33.871
  text "1" at 18.792,204.127 h1.78
  text "2" at 82.182,204.127 h1.78
  text "3" at 145.411,204.127 h1.78
  text "4" at 209.08,204.127 h1.78
  text "5" at 272.555,204.127 h1.78
  text "6" at 336.182,204.127 h1.78
  text "A" at -10.579,175.095 h1.78
  text "A" at 365.341,175.095 h1.78
  text "B" at -10.579,114.643 h1.78
  text "B" at 365.341,114.643 h1.78
  text "C" at -10.579,54.318 h1.78
  text "C" at 365.341,54.318 h1.78
  text "PROJECT TITLE:" at 288.125,7.048 h1.14
  text ".PRJ_Title" at 289.395,3.662 h1.78
  text "DESIGNED FOR:" at 288.125,-0.597 h1.14
  text ".PRJ_Customer" at 289.395,-4.153 h1.78
  text "D" at -10.579,-5.88 h1.78
  text "D" at 365.341,-5.88 h1.78
  text "FILE NAME:" at 288.125,-8.217 h1.14
  text ".PCB_File_Name_No_Path" at 289.395,-11.265 h1.78
  text "Texas Instruments (TI) and/or its licensors do not warrant the accuracy or completeness of this specification" at 161.9,-15.376 h1.14
  text "ENGINEER:" at 288.125,-15.583 h1.14
  text "LAYOUT BY:" at 326.352,-15.583 h1.14
  text "or any information contained therein. TI and/or its licensors do not warrant that this design will meet" at 160.757,-18.237 h1.14
  text ".PRJ_Engineer" at 289.395,-19.52 h1.78
  text ".PCB_Layout" at 327.635,-19.52 h1.78
  text "the specifications, will be suitable for your application or fit for any particular purpose, or will operate in" at 160.757,-21.099 h1.14
  text ".Layer_Name" at 14.656,-21.806 h1.52
  text "ALTIUM DESIGNER VERSION:" at 326.352,-23.457 h1.14
  text "an implementation. TI and/or its licensors do not warrant that the design is production worthy. You should" at 160.757,-23.961 h1.14
  text "completely validate and test your design implementation to confirm the system functionality for your application." at 161.9,-26.822 h1.14
  text ".print_Scale" at 289.395,-26.843 h1.78
  text ".Application_BuildNumber" at 327.635,-26.843 h1.78
  text "1" at 18.792,-32.093 h1.78
  text "2" at 82.182,-32.093 h1.78
  text "3" at 145.411,-32.093 h1.78
  text "4" at 209.08,-32.093 h1.78
  text "5" at 272.555,-32.093 h1.78
  text "6" at 336.182,-32.093 h1.78
M10 Fab Notes:
  drawing of 189 lines, arcs and shapes, not listed
  text "DESIGN INFORMATION" at 314.503,161.447 h1.52
  text "MIN. TRACK WIDTH:" at 298.131,158.091 h1.52
  text "8" at 325.976,158.091 h1.52
  text "MIL" at 329.907,158.091 h1.52
  text "MIN. CLEARANCE:" at 298.131,154.938 h1.52
  text "MIL" at 329.907,154.938 h1.52
  text "8" at 326.2,154.8 h1.52
  text "MIN. VIA PAD SIZE:" at 298.131,151.785 h1.52
  text "19" at 325.214,151.785 h1.52
  text "MIL" at 329.907,151.785 h1.52
  text "0.05mm (2MIL)" at 315.784,148.486 h1.52
  text "MINIMUM ANNULAR RING" at 289.769,148.277 h1.52
  text "EXTERNAL" at 333.768,148.277 h1.52
  text "PER" at 294.849,145.48 h1.52
  text "IPC-D-275 CLASS 2 LEVEL C" at 300.437,145.48 h1.52
  text "MIL, HOLES" at 338.238,142.928 h1.52
  text "+/-" at 328.27,142.709 h1.52
  text "+/-" at 349.961,142.709 h1.52
  text "REGISTRATION TOLERANCES:" at 289.769,142.682 h1.52
  text "METAL" at 320.243,142.682 h1.52
  text "5" at 334.879,142.683 h1.52
  text "3" at 356.037,142.683 h1.52
  text "MIL" at 358.99,142.682 h1.52
  text "HOLE SIZE TOLERANCE (UNLESS OTHERWISE SPECIFIED):" at 289.769,140.185 h1.52
  text "+/-" at 349.961,140.112 h1.52
  text "3" at 356.037,140.085 h1.52
  text "MIL" at 358.99,140.085 h1.52
  text "MATERIAL:" at 287.87,136.589 h1.52
  text "FR-4 High Tg" at 312.926,133.324 h1.52
  text "X" at 309.257,133.122 h1.52
  text "FR-4" at 298.563,133.007 h1.52
  text "OTHER" at 336.358,133.007 h1.52
  text "62 MIL (1.6mm) +/-10%" at 306.694,129.374 h1.52
  text "X" at 303.643,129.312 h1.52
  text "THICKNESS:" at 289.769,129.165 h1.52
  text "OTHER" at 339.33,129.165 h1.52
  text "TOLERANCE:" at 289.769,125.652 h1.52
  text "X" at 311.314,125.652 h1.52
  text "ANSI IPC-6012 TYPE 3 CLASS 2" at 315.836,125.652 h1.52
  text "OTHER +/-" at 315.835,121.989 h1.52
  text "BOW & TWIST:" at 289.769,118.302 h1.52
  text "X" at 311.314,118.302 h1.52
  text "ANSI IPC-6012 TYPE 3 CLASS 2" at 315.836,118.302 h1.52
  text "OTHER +/-" at 315.835,114.576 h1.52
  text "DRILLING:" at 287.87,111.258 h1.52
  text "NC_DRILL FILES" at 332.599,108.586 h1.52
  text "REFERENCE:" at 289.769,108.486 h1.52
  text "X" at 306.463,108.484 h1.52
  text "AS SHOWN" at 310.984,108.486 h1.52
  text "X" at 329.348,108.486 h1.52
  text "OTHER" at 340.168,104.873 h1.52
  text "PTH COPPER THICKNESS:" at 289.761,104.783 h1.52
  text "X" at 318.697,104.783 h1.52
  text "20-30 um" at 321.948,104.783 h1.52
  text "BOARD FINISH:" at 287.87,101.034 h1.52
  text "SILKSCREEN:" at 291.812,98.237 h1.52
  text "X" at 316.14,98.237 h1.52
  text "TOP" at 319.112,98.237 h1.52
  text "X" at 329.094,98.237 h1.52
  text "BOTTOM" at 332.091,98.237 h1.52
  text "SILKSCREEN COLOR:" at 291.812,94.295 h1.52
  text "X" at 316.115,94.295 h1.52
  text "WHITE" at 319.112,94.295 h1.52
  text "OTHER" at 332.091,94.295 h1.52
  text "X" at 319.442,90.652 h1.52
  text "GREEN" at 322.439,90.652 h1.52
  text "OTHER" at 338.136,90.652 h1.52
  text "SOLDER RESIST COLOR:" at 291.812,90.477 h1.52
  text "X" at 319.442,86.734 h1.52
  text "MATTE" at 322.439,86.734 h1.52
  text "SEMI-GLOSS" at 338.125,86.717 h1.52
  text "IMMERSION GOLD (ENIG)" at 314.819,82.345 h1.52
  text "ENEPIG" at 348.793,82.162 h1.52
  text "SURFACE FINISH:" at 287.87,82.136 h1.52
  text "HASL" at 342.237,78.762 h1.52
  text "IMM. TIN/SILVER OR EQUIV" at 296.24,78.649 h1.52
  text "X" at 328.078,78.549 h1.52
  text "OTHER" at 332.599,78.549 h1.52
  text "ARRAY/PANEL:" at 287.87,74.602 h1.52
  text "CUT AND TRIM PER M1 BOARD OUTLINE" at 314.819,74.393 h1.52
  text "N.C. ROUTE" at 314.819,70.94 h1.52
  text "X" at 332.295,70.94 h1.52
  text "V. SCORE" at 336.816,70.94 h1.52
  text "CERTIFICATION:" at 287.87,67.66 h1.52
  text "MATERIALS AND WORKMANSHIP FOR ALL PCBS" at 306.285,67.66 h1.52
  text "TO MEET OR EXCEED THE REQUIREMENTS OF:" at 306.285,65.271 h1.52
  text "X" at 297.078,62.003 h1.52
  text "ANSI IPC-A-600F CLASS ->" at 300.329,62.003 h1.52
  text "X" at 342.188,62.003 h1.52
  text "2" at 344.982,62.003 h1.52
  text "1" at 336.981,61.965 h1.52
  text "3" at 353.973,61.965 h1.52
  text "X" at 317.702,58.252 h1.52
  text "RoHS" at 320.953,58.252 h1.52
  text "OTHER" at 337.321,58.252 h1.52
  text "PER ORDER" at 347.407,58.252 h1.52
  text "ALL BOARDS MUST MEET OR EXCEED UL94-V0 REQUIREMENTS." at 288.569,54.345 h1.52
  text "PCB MUST BEAR THE UL94V-0 UL REGISTERED MATERIAL ID NUMBER" at 288.569,51.397 h1.52
  text "ADDITIONAL REQUIREMENTS:" at 287.87,47.094 h1.52
  text "MICROSECTION:" at 289.769,44.373 h1.52
  text "YES" at 312.775,44.373 h1.52
  text "REQUIRED" at 334.657,40.707 h1.52
  text "BARE BOARD ELEC. TEST:" at 289.769,40.634 h1.52
  text "NONE" at 322.935,40.634 h1.52
  text "X" at 331.66,40.634 h1.52
  text "PER ORDER" at 349.693,40.634 h1.52
  text "XX MIL VIAS REQUIRE NON-CONDUCTIVE FILL AND PLANARIZE" at 294.04,35.428 h1.5
  text "XX MIL VIAS REQUIRE CONDUCTIVE FILL AND PLANARIZE" at 294.243,32.787 h1.52
  text "OUTER XX MIL TRACES REQUIRE 50 OHM SINGLE-ENDED IMPEDANCE" at 294.218,28.637 h1.47
  text "LAYER 2 & 3 (INNER LAYERS) XX MIL WIDE, XX MIL SPACE / TRACES REQUIRE 100 OHM DIFFERENTIAL IMPEDANCE" at 294.015,22.65 h1.52
  text ".Layer_Name" at 14.656,-21.806 h1.52
M11 Gerber Information:
  lines w0.254: -7.417,-23.626 160.223,-23.626 ; -7.417,-18.462 160.274,-18.462 ; -7.417,-13.297 -7.417,-28.791 94.31,-28.791 160.274,-28.791 160.274,-13.297 -7.404,-13.297 -7.404,-28.791 32.614,-28.791 ; 55.194,-28.791 55.194,-13.297 ; 87.376,-18.462 87.376,-13.297 ; 108.712,-18.462 108.712,-13.297 ; 124.511,-28.956 124.511,-23.804
  text "ALL ARTWORK VIEWED FROM TOP SIDE" at -5.804,-16.654 h1.52
  text "BOARD #:" at 57.099,-16.654 h1.52
  text ".PRJ_Number" at 70.955,-16.654 h1.52
  text "REV:" at 92.405,-16.654 h1.52
  text ".PCB_Rev" at 99.809,-16.654 h1.52
  text "SVN REV:" at 113.69,-16.654 h1.52
  text ".VersionControl_RevNumber" at 126.543,-16.654 h1.52
  text "LAYER NAME =" at -5.804,-21.806 h1.52
  text "TID #:" at 57.099,-21.819 h1.52
  text ".TID" at 70.955,-21.819 h1.52
  text "PLOT NAME =" at -5.804,-27.034 h1.52
  text ".plot_File_Name" at 14.656,-27.034 h1.52
  text "GENERATED    :" at 57.15,-27.034 h1.52
  text ".Print_Date" at 79.235,-27.034 h1.52
  text ".Print_Time" at 97.752,-27.034 h1.52
  text "TEXAS INSTRUMENTS" at 129.87,-27.034 h1.52
M12 Stackup:
  lines w0.025: 295.015,179.003 296.985,180.973 300.033,184.021 303.081,187.069 306.129,190.117 309.177,193.165 ; 295.015,180.527 295.461,180.973 298.509,184.021 301.557,187.069 304.605,190.117 307.653,193.165 309.177,194.689 ; 295.015,182.051 296.985,184.021 300.033,187.069 303.081,190.117 306.129,193.165 309.177,196.213 ; 295.015,183.575 295.461,184.021 298.509,187.069 301.557,190.117 304.605,193.165 307.653,196.213 309.177,197.737 ; 295.015,185.099 296.985,187.069 300.033,190.117 303.081,193.165 306.129,196.213 309.177,199.261 ; 295.015,186.623 295.461,187.069 298.509,190.117 301.557,193.165 304.605,196.213 307.653,199.261 ; 295.015,188.147 296.985,190.117 300.033,193.165 303.081,196.213 306.129,199.261 ; 295.015,189.671 295.461,190.117 298.509,193.165 301.557,196.213 304.605,199.261 ; 295.015,191.195 296.985,193.165 300.033,196.213 303.081,199.261 ; 295.015,192.719 295.461,193.165 298.509,196.213 301.557,199.261 ; 295.015,194.243 296.985,196.213 300.033,199.261 ; 295.015,195.767 295.461,196.213 298.509,199.261 ; 295.015,197.291 296.985,199.261 ; 295.015,198.815 295.461,199.261 ; 295.461,177.925 298.509,180.973 301.557,184.021 304.605,187.069 307.653,190.117 309.177,191.641 ; 296.985,177.925 300.033,180.973 303.081,184.021 306.129,187.069 309.177,190.117 ; 298.509,177.925 301.557,180.973 304.605,184.021 307.653,187.069 309.177,188.593 ; 300.033,177.925 303.081,180.973 306.129,184.021 309.177,187.069 ; 301.557,177.925 304.605,180.973 307.653,184.021 309.177,185.545 ; 303.081,177.925 306.129,180.973 309.177,184.021 ; 304.605,177.925 307.653,180.973 309.177,182.497 ; 306.129,177.925 309.177,180.973 ; 307.653,177.925 309.177,179.449
  lines w0.381: 247.691,180.973 254.068,180.973 266.402,180.973 277.485,180.973 286.589,180.973 295.015,180.973 309.177,180.973 ; 247.691,184.021 254.068,184.021 266.402,184.021 277.485,184.021 286.589,184.021 295.015,184.021 309.177,184.021 ; 247.691,187.069 254.068,187.069 266.402,187.069 277.485,187.069 286.589,187.069 295.015,187.069 309.177,187.069 ; 247.691,190.117 254.068,190.117 266.402,190.117 277.485,190.117 286.589,190.117 295.015,190.117 309.177,190.117 ; 247.691,193.165 254.068,193.165 266.402,193.165 277.485,193.165 286.589,193.165 295.015,193.165 309.177,193.165 ; 247.691,196.213 254.068,196.213 266.402,196.213 277.485,196.213 286.589,196.213 295.015,196.213 309.177,196.213 ; 247.691,199.261 309.177,199.261 ; 254.068,202.309 254.068,177.925 ; 266.402,202.309 266.402,177.925 ; 277.485,202.309 277.485,177.925 ; 286.589,202.309 286.589,177.925 ; 295.015,202.309 295.015,177.925 ; 254.068,177.925 247.691,177.925 247.691,202.309 309.177,202.309 309.177,177.925 295.015,177.925 ; 254.068,177.925 266.402,177.925 ; 266.402,177.925 277.485,177.925 ; 277.485,177.925 286.589,177.925 ; 286.589,177.925 295.015,177.925
  text "Layer" at 249.215,200.023 h1.52
  text "Name" at 255.592,200.023 h1.52
  text "Material" at 267.926,200.023 h1.52
  text "Thickness" at 279.009,200.023 h1.52
  text "Constant" at 288.113,200.023 h1.52
  text "Board Layer Stack" at 296.539,200.023 h1.52
  text "Top Overlay" at 255.592,196.975 h1.52
  text "Top Solder" at 255.592,193.927 h1.52
  text "Solder Resist" at 267.926,193.927 h1.52
  text "0.010mm" at 279.009,193.927 h1.52
  text "3.5" at 288.113,193.927 h1.52
  text "1" at 249.215,190.879 h1.52
  text "Top Layer" at 255.592,190.879 h1.52
  text "0.070mm" at 279.009,190.879 h1.52
  text "Dielectric1" at 255.592,187.831 h1.52
  text "FR-4 High Tg" at 267.926,187.831 h1.52
  text "1.460mm" at 279.009,187.831 h1.52
  text "4.8" at 288.113,187.831 h1.52
  text "2" at 249.213,184.783 h1.52
  text "Bottom Layer" at 255.592,184.783 h1.52
  text "0.070mm" at 279.009,184.783 h1.52
  text "Bottom Solder" at 255.592,181.735 h1.52
  text "Solder Resist" at 267.926,181.735 h1.52
  text "0.010mm" at 279.009,181.735 h1.52
  text "3.5" at 288.113,181.735 h1.52
  text "Bottom Overlay" at 255.592,178.687 h1.52
  text ".Layer_Name" at 14.656,-21.806 h1.52
M13 Component Bodies Top:
  text ".Layer_Name" at 14.656,-21.806 h1.52
M14 Component Bodies Bottom:
  text ".Layer_Name" at 14.656,-21.806 h1.52
M15 Courtyards Top:
  text ".Layer_Name" at 14.656,-21.806 h1.52
M16 Courtyards Bottom:
  text ".Layer_Name" at 14.656,-21.806 h1.52
Drill Drawing:
  drawing of 186 lines, arcs and shapes, not listed
  text "Symbol" at -1.124,164.113 h1.83
  text "Count" at 11.726,164.113 h1.83
  text "Hole Size" at 26.962,164.113 h1.83
  text "Plated" at 56.417,164.113 h1.83
  text "Hole Type" at 69.266,164.113 h1.83
  text "Drill Layer Pair" at 87.905,164.113 h1.83
  text "Via/Pad" at 125.993,164.113 h1.83
  text "Pad Shape" at 140.976,164.113 h1.83
  text "Template" at 159.919,164.113 h1.83
  text "1" at 11.726,160.303 h1.52
  text "3.200mm (125.98mil)" at 26.962,160.303 h1.52
  text "NPTH" at 56.417,160.303 h1.52
  text "Round" at 69.266,160.303 h1.52
  text "Top Layer - Bottom Layer" at 87.905,160.303 h1.52
  text "Pad" at 125.993,160.303 h1.52
  text "Rounded" at 140.976,160.303 h1.52
  text "c0hn320" at 159.919,160.303 h1.52
  text "D" at -1.862,160.05 h1.69
  text "1" at 11.726,156.493 h1.52
  text "6.000mm (236.22mil)" at 26.962,156.493 h1.52
  text "NPTH" at 56.417,156.493 h1.52
  text "Round" at 69.266,156.493 h1.52
  text "Top Layer - Bottom Layer" at 87.905,156.493 h1.52
  text "Pad" at 125.993,156.493 h1.52
  text "Rounded" at 140.976,156.493 h1.52
  text "c600hn600m600p-1" at 159.919,156.493 h1.52
  text "2" at 11.726,152.683 h1.52
  text "1.100mm (43.31mil)" at 26.962,152.683 h1.52
  text "PTH" at 56.417,152.683 h1.52
  text "Round" at 69.266,152.683 h1.52
  text "Top Layer - Bottom Layer" at 87.905,152.683 h1.52
  text "Pad" at 125.993,152.683 h1.52
  text "Rounded" at 140.976,152.683 h1.52
  text "c160h110" at 159.919,152.683 h1.52
  text "2" at 11.726,148.873 h1.52
  text "2.000mm (78.74mil)" at 26.962,148.873 h1.52
  text "PTH" at 56.417,148.873 h1.52
  text "Round" at 69.266,148.873 h1.52
  text "Top Layer - Bottom Layer" at 87.905,148.873 h1.52
  text "Pad" at 125.993,148.873 h1.52
  text "(Mixed)" at 140.976,148.873 h1.52
  text "(Mixed)" at 159.919,148.873 h1.52
  text "2" at 11.726,145.063 h1.52
  text "7.000mm (275.59mil)" at 26.962,145.063 h1.52
  text "NPTH" at 56.417,145.063 h1.52
  text "Round" at 69.266,145.063 h1.52
  text "Top Layer - Bottom Layer" at 87.905,145.063 h1.52
  text "Pad" at 125.993,145.063 h1.52
  text "Rounded" at 140.976,145.063 h1.52
  text "c700hn700m700p-1" at 159.919,145.063 h1.52
  text "4" at 11.726,141.253 h1.52
  text "1.000mm (39.37mil)" at 26.962,141.253 h1.52
  text "PTH" at 56.417,141.253 h1.52
  text "Round" at 69.266,141.253 h1.52
  text "Top Layer - Bottom Layer" at 87.905,141.253 h1.52
  text "Pad" at 125.993,141.253 h1.52
  text "(Mixed)" at 140.976,141.253 h1.52
  text "(Mixed)" at 159.919,141.253 h1.52
  text "4" at 11.726,137.443 h1.52
  text "1.090mm (42.91mil)" at 26.962,137.443 h1.52
  text "PTH" at 56.417,137.443 h1.52
  text "Round" at 69.266,137.443 h1.52
  text "Top Layer - Bottom Layer" at 87.905,137.443 h1.52
  text "Pad" at 125.993,137.443 h1.52
  text "(Mixed)" at 140.976,137.443 h1.52
  text "(Mixed)" at 159.919,137.443 h1.52
  text "A" at -1.862,137.19 h1.69
  text "4" at 11.726,133.633 h1.52
  text "1.200mm (47.24mil)" at 26.962,133.633 h1.52
  text "PTH" at 56.417,133.633 h1.52
  text "Round" at 69.266,133.633 h1.52
  text "Top Layer - Bottom Layer" at 87.905,133.633 h1.52
  text "Pad" at 125.993,133.633 h1.52
  text "(Mixed)" at 140.976,133.633 h1.52
  text "(Mixed)" at 159.919,133.633 h1.52
  text "4" at 11.726,129.823 h1.52
  text "1.600mm (62.99mil)" at 26.962,129.823 h1.52
  text "PTH" at 56.417,129.823 h1.52
  text "Round" at 69.266,129.823 h1.52
  text "Top Layer - Bottom Layer" at 87.905,129.823 h1.52
  text "Pad" at 125.993,129.823 h1.52
  text "(Mixed)" at 140.976,129.823 h1.52
  text "(Mixed)" at 159.919,129.823 h1.52
  text "4" at 11.726,126.013 h1.52
  text "2.000mm (78.74mil)" at 26.962,126.013 h1.52
  text "NPTH" at 56.417,126.013 h1.52
  text "Round" at 69.266,126.013 h1.52
  text "Top Layer - Bottom Layer" at 87.905,126.013 h1.52
  text "Pad" at 125.993,126.013 h1.52
  text "Rounded" at 140.976,126.013 h1.52
  text "c200hn200" at 159.919,126.013 h1.52
  text "4" at 11.726,122.203 h1.52
  text "3.150mm (124.02mil)" at 26.962,122.203 h1.52
  text "NPTH" at 56.417,122.203 h1.52
  text "Round" at 69.266,122.203 h1.52
  text "Top Layer - Bottom Layer" at 87.905,122.203 h1.52
  text "Pad" at 125.993,122.203 h1.52
  text "Rounded" at 140.976,122.203 h1.52
  text "c315hn315m315p-1" at 159.919,122.203 h1.52
  text "14" at 11.726,118.393 h1.52
  text "1.300mm (51.18mil)" at 26.962,118.393 h1.52
  text "PTH" at 56.417,118.393 h1.52
  text "Round" at 69.266,118.393 h1.52
  text "Top Layer - Bottom Layer" at 87.905,118.393 h1.52
  text "Pad" at 125.993,118.393 h1.52
  text "(Mixed)" at 140.976,118.393 h1.52
  text "(Mixed)" at 159.919,118.393 h1.52
  text "16" at 11.726,114.583 h1.52
  text "0.300mm (11.81mil)" at 26.962,114.583 h1.52
  text "PTH" at 56.417,114.583 h1.52
  text "Round" at 69.266,114.583 h1.52
  text "Top Layer - Bottom Layer" at 87.905,114.583 h1.52
  text "Via" at 125.993,114.583 h1.52
  text "Rounded" at 140.976,114.583 h1.52
  text "(Mixed)" at 159.919,114.583 h1.52
  text "17" at 11.726,110.773 h1.52
  text "0.900mm (35.43mil)" at 26.962,110.773 h1.52
  text "PTH" at 56.417,110.773 h1.52
  text "Round" at 69.266,110.773 h1.52
  text "Top Layer - Bottom Layer" at 87.905,110.773 h1.52
  text "Pad" at 125.993,110.773 h1.52
  text "(Mixed)" at 140.976,110.773 h1.52
  text "(Mixed)" at 159.919,110.773 h1.52
  text "23" at 11.726,106.963 h1.52
  text "0.750mm (29.53mil)" at 26.962,106.963 h1.52
  text "PTH" at 56.417,106.963 h1.52
  text "Round" at 69.266,106.963 h1.52
  text "Top Layer - Bottom Layer" at 87.905,106.963 h1.52
  text "Pad" at 125.993,106.963 h1.52
  text "(Mixed)" at 140.976,106.963 h1.52
  text "(Mixed)" at 159.919,106.963 h1.52
  text "46" at 11.726,103.153 h1.52
  text "1.020mm (40.16mil)" at 26.962,103.153 h1.52
  text "PTH" at 56.417,103.153 h1.52
  text "Round" at 69.266,103.153 h1.52
  text "Top Layer - Bottom Layer" at 87.905,103.153 h1.52
  text "Pad" at 125.993,103.153 h1.52
  text "(Mixed)" at 140.976,103.153 h1.52
  text "(Mixed)" at 159.919,103.153 h1.52
  text "180" at 11.726,99.343 h1.52
  text "0.200mm (7.87mil)" at 26.962,99.343 h1.52
  text "PTH" at 56.417,99.343 h1.52
  text "Round" at 69.266,99.343 h1.52
  text "Top Layer - Bottom Layer" at 87.905,99.343 h1.52
  text "Via" at 125.993,99.343 h1.52
  text "Rounded" at 140.976,99.343 h1.52
  text "(Mixed)" at 159.919,99.343 h1.52
  text "328 Total" at 11.726,95.533 h1.52
  text ".Layer_Name" at 14.656,-21.806 h1.52
M17 Embedded Cavity:
  text ".Layer_Name" at 14.656,-21.806 h1.52
M18 Embedded Assembly:
  text ".Layer_Name" at 14.656,-21.806 h1.52
M19 Embedded Keepout:
  text ".Layer_Name" at 14.656,-21.806 h1.52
